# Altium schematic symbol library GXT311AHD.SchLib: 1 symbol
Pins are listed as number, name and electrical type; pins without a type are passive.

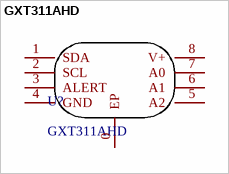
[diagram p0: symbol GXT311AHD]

## GXT311AHD
designator U?
footprint DFN-8-EP_L3.0-W3.0-P0.65
pins: 0 EP, 1 SDA, 2 SCL, 3 ALERT, 4 GND, 5 A2, 6 A1, 7 A0, 8 V+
